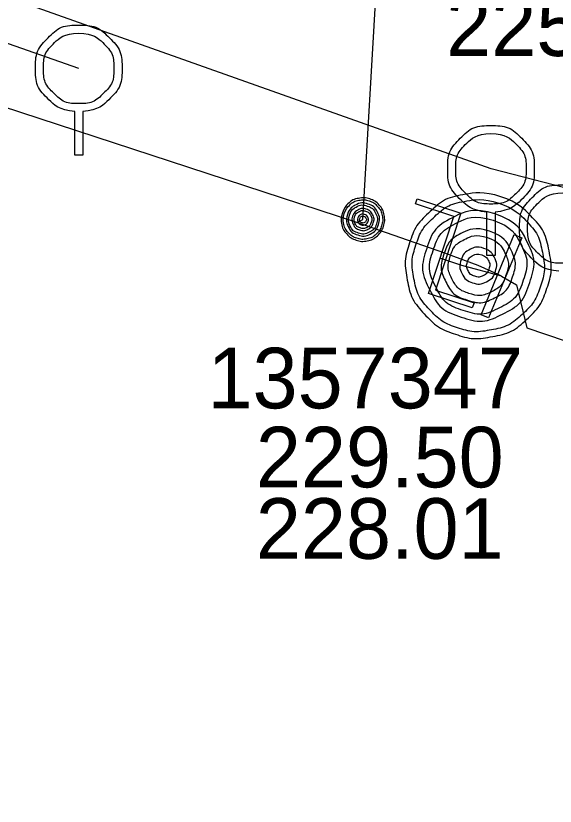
# Model space of a CAD drawing. Extents: x -595129 to -593591, y -1168385 to -1166898.
# Drawn here: x -594582.79 to -594570.33, y -1167194.67 to -1167176.41 of the extents above; entities that cross this region are included whole.
import ezdxf

# ---------------------------------------------------------------- set-up
doc = ezdxf.new("R2010")
doc.units = 0
for name, color, linetype in [('Default', 7, 'Continuous'), ('Identifikace', 7, 'Continuous'), ('Kanalizační stoka', 7, 'Continuous'), ('Kanalizační šachta', 7, 'Continuous'), ('Popis šachty', 7, 'Continuous'), ('V Lomový bod', 7, 'Continuous'), ('V Přípojka', 7, 'Continuous'), ('V Uzávěr', 7, 'Continuous'), ('V Řad', 7, 'Continuous')]:
    doc.layers.add(name, color=color, linetype=linetype)

msp = doc.modelspace()

# ---------------------------------------------------------------- linework, layer by layer
at = {"layer": 'Default'}
for points in [[(-594581.429, -1167178.626), (-594581.782, -1167178.597), (-594582.042, -1167178.337), (-594582.335, -1167178.046), (-594582.335, -1167177.632), (-594582.335, -1167177.216), (-594582.045, -1167176.923), (-594581.755, -1167176.63), (-594581.337, -1167176.63), (-594580.917, -1167176.63), (-594580.626, -1167176.923), (-594580.335, -1167177.216), (-594580.335, -1167177.632), (-594580.335, -1167178.046), (-594580.628, -1167178.337), (-594580.886, -1167178.597), (-594581.241, -1167178.626)], [(-594581.337, -1167176.816), (-594581.675, -1167176.816), (-594581.912, -1167177.053), (-594582.149, -1167177.29), (-594582.149, -1167177.628), (-594582.149, -1167177.966), (-594581.912, -1167178.203), (-594581.675, -1167178.441), (-594581.337, -1167178.441), (-594580.999, -1167178.441), (-594580.762, -1167178.203), (-594580.524, -1167177.966), (-594580.524, -1167177.628), (-594580.524, -1167177.29), (-594580.761, -1167177.053), (-594580.997, -1167176.816), (-594581.337, -1167176.816)], [(-594571.904, -1167180.946), (-594572.257, -1167180.917), (-594572.517, -1167180.657), (-594572.81, -1167180.366), (-594572.81, -1167179.952), (-594572.81, -1167179.536), (-594572.52, -1167179.243), (-594572.23, -1167178.95), (-594571.812, -1167178.95), (-594571.392, -1167178.95), (-594571.101, -1167179.243), (-594570.81, -1167179.536), (-594570.81, -1167179.952), (-594570.81, -1167180.366), (-594571.103, -1167180.657), (-594571.361, -1167180.917), (-594571.716, -1167180.946)], [(-594571.812, -1167179.136), (-594572.15, -1167179.136), (-594572.387, -1167179.373), (-594572.624, -1167179.61), (-594572.624, -1167179.948), (-594572.624, -1167180.286), (-594572.387, -1167180.523), (-594572.15, -1167180.761), (-594571.812, -1167180.761), (-594571.474, -1167180.761), (-594571.237, -1167180.523), (-594570.999, -1167180.286), (-594570.999, -1167179.948), (-594570.999, -1167179.61), (-594571.236, -1167179.373), (-594571.472, -1167179.136), (-594571.812, -1167179.136)], [(-594571.582, -1167180.594), (-594571.182, -1167180.727), (-594570.87, -1167181.057), (-594570.558, -1167181.387), (-594570.469, -1167181.84), (-594570.381, -1167182.293), (-594570.518, -1167182.708), (-594570.654, -1167183.121), (-594570.988, -1167183.429), (-594571.322, -1167183.737), (-594571.77, -1167183.821), (-594572.217, -1167183.906), (-594572.631, -1167183.769), (-594573.042, -1167183.633), (-594573.351, -1167183.299), (-594573.66, -1167182.965), (-594573.744, -1167182.518), (-594573.829, -1167182.072), (-594573.692, -1167181.659), (-594573.555, -1167181.244), (-594573.216, -1167180.932), (-594572.876, -1167180.621), (-594572.43, -1167180.541), (-594571.983, -1167180.462), (-594571.582, -1167180.594)], [(-594570.244, -1167182.316), (-594570.597, -1167182.287), (-594570.857, -1167182.027), (-594571.15, -1167181.736), (-594571.15, -1167181.322), (-594571.15, -1167180.906), (-594570.86, -1167180.613), (-594570.57, -1167180.32), (-594570.152, -1167180.32), (-594569.732, -1167180.32), (-594569.441, -1167180.613), (-594569.15, -1167180.906), (-594569.15, -1167181.322), (-594569.15, -1167181.736), (-594569.443, -1167182.027), (-594569.701, -1167182.287), (-594570.056, -1167182.316)], [(-594575.245, -1167180.963), (-594575.205, -1167180.844), (-594575.107, -1167180.75), (-594575.008, -1167180.657), (-594574.872, -1167180.63), (-594574.737, -1167180.604), (-594574.612, -1167180.645), (-594574.489, -1167180.685), (-594574.396, -1167180.785), (-594574.304, -1167180.885), (-594574.279, -1167181.019), (-594574.253, -1167181.153), (-594574.294, -1167181.277), (-594574.335, -1167181.4), (-594574.435, -1167181.493), (-594574.535, -1167181.585), (-594574.669, -1167181.611), (-594574.802, -1167181.636), (-594574.926, -1167181.595), (-594575.05, -1167181.554), (-594575.144, -1167181.453), (-594575.237, -1167181.351), (-594575.261, -1167181.217), (-594575.285, -1167181.084), (-594575.245, -1167180.963)], [(-594571.631, -1167180.743), (-594571.994, -1167180.623), (-594572.399, -1167180.695), (-594572.804, -1167180.766), (-594573.112, -1167181.049), (-594573.419, -1167181.332), (-594573.544, -1167181.708), (-594573.667, -1167182.082), (-594573.591, -1167182.486), (-594573.515, -1167182.89), (-594573.234, -1167183.194), (-594572.954, -1167183.497), (-594572.582, -1167183.62), (-594572.206, -1167183.744), (-594571.8, -1167183.668), (-594571.394, -1167183.591), (-594571.092, -1167183.312), (-594570.79, -1167183.033), (-594570.667, -1167182.659), (-594570.542, -1167182.282), (-594570.623, -1167181.872), (-594570.704, -1167181.461), (-594570.986, -1167181.162), (-594571.268, -1167180.863), (-594571.631, -1167180.743)], [(-594570.152, -1167180.506), (-594570.49, -1167180.506), (-594570.727, -1167180.743), (-594570.964, -1167180.98), (-594570.964, -1167181.318), (-594570.964, -1167181.656), (-594570.727, -1167181.893), (-594570.49, -1167182.131), (-594570.152, -1167182.131), (-594569.814, -1167182.131), (-594569.577, -1167181.893), (-594569.339, -1167181.656), (-594569.339, -1167181.318), (-594569.339, -1167180.98), (-594569.576, -1167180.743), (-594569.812, -1167180.506), (-594570.152, -1167180.506)], [(-594575.2, -1167180.978), (-594575.236, -1167181.087), (-594575.215, -1167181.208), (-594575.193, -1167181.329), (-594575.109, -1167181.421), (-594575.024, -1167181.513), (-594574.911, -1167181.551), (-594574.799, -1167181.588), (-594574.678, -1167181.565), (-594574.557, -1167181.542), (-594574.466, -1167181.458), (-594574.376, -1167181.374), (-594574.339, -1167181.262), (-594574.302, -1167181.15), (-594574.325, -1167181.029), (-594574.348, -1167180.907), (-594574.431, -1167180.817), (-594574.515, -1167180.726), (-594574.627, -1167180.689), (-594574.74, -1167180.652), (-594574.863, -1167180.676), (-594574.986, -1167180.701), (-594575.075, -1167180.785), (-594575.164, -1167180.87), (-594575.2, -1167180.978)], [(-594575.126, -1167181.003), (-594575.077, -1167180.853), (-594574.938, -1167180.784), (-594574.799, -1167180.715), (-594574.651, -1167180.764), (-594574.504, -1167180.812), (-594574.434, -1167180.951), (-594574.364, -1167181.09), (-594574.413, -1167181.238), (-594574.462, -1167181.385), (-594574.6, -1167181.455), (-594574.739, -1167181.525), (-594574.887, -1167181.476), (-594575.035, -1167181.428), (-594575.105, -1167181.29), (-594575.175, -1167181.152), (-594575.126, -1167181.003)], [(-594575.083, -1167181.018), (-594575.125, -1167181.147), (-594575.064, -1167181.269), (-594575.003, -1167181.39), (-594574.874, -1167181.432), (-594574.744, -1167181.475), (-594574.623, -1167181.414), (-594574.502, -1167181.353), (-594574.459, -1167181.223), (-594574.416, -1167181.094), (-594574.477, -1167180.973), (-594574.538, -1167180.851), (-594574.668, -1167180.809), (-594574.797, -1167180.766), (-594574.918, -1167180.826), (-594575.04, -1167180.887), (-594575.083, -1167181.018)], [(-594571.714, -1167180.991), (-594571.214, -1167181.156), (-594570.983, -1167181.619), (-594570.751, -1167182.083), (-594570.915, -1167182.577), (-594571.078, -1167183.07), (-594571.541, -1167183.303), (-594572.005, -1167183.535), (-594572.501, -1167183.372), (-594572.991, -1167183.21), (-594573.225, -1167182.746), (-594573.458, -1167182.283), (-594573.296, -1167181.79), (-594573.132, -1167181.296), (-594572.671, -1167181.061), (-594572.21, -1167180.827), (-594571.714, -1167180.991)], [(-594575.007, -1167181.042), (-594574.974, -1167180.942), (-594574.882, -1167180.896), (-594574.789, -1167180.85), (-594574.691, -1167180.882), (-594574.592, -1167180.915), (-594574.546, -1167181.007), (-594574.499, -1167181.1), (-594574.532, -1167181.199), (-594574.564, -1167181.297), (-594574.657, -1167181.343), (-594574.749, -1167181.39), (-594574.847, -1167181.358), (-594574.946, -1167181.325), (-594574.993, -1167181.233), (-594575.04, -1167181.141), (-594575.007, -1167181.042)], [(-594574.963, -1167181.056), (-594574.99, -1167181.137), (-594574.952, -1167181.212), (-594574.914, -1167181.287), (-594574.834, -1167181.313), (-594574.754, -1167181.34), (-594574.679, -1167181.302), (-594574.604, -1167181.264), (-594574.577, -1167181.184), (-594574.551, -1167181.104), (-594574.588, -1167181.029), (-594574.626, -1167180.954), (-594574.706, -1167180.927), (-594574.787, -1167180.901), (-594574.862, -1167180.938), (-594574.937, -1167180.976), (-594574.963, -1167181.056)], [(-594574.888, -1167181.081), (-594574.872, -1167181.031), (-594574.826, -1167181.008), (-594574.779, -1167180.985), (-594574.73, -1167181.001), (-594574.681, -1167181.017), (-594574.658, -1167181.064), (-594574.634, -1167181.11), (-594574.651, -1167181.16), (-594574.667, -1167181.208), (-594574.713, -1167181.232), (-594574.759, -1167181.255), (-594574.809, -1167181.239), (-594574.858, -1167181.222), (-594574.881, -1167181.176), (-594574.905, -1167181.13), (-594574.888, -1167181.081)], [(-594571.763, -1167181.136), (-594572.197, -1167180.993), (-594572.601, -1167181.197), (-594573.005, -1167181.401), (-594573.148, -1167181.834), (-594573.291, -1167182.266), (-594573.088, -1167182.671), (-594572.885, -1167183.076), (-594572.451, -1167183.22), (-594572.019, -1167183.363), (-594571.613, -1167183.159), (-594571.208, -1167182.955), (-594571.065, -1167182.522), (-594570.922, -1167182.09), (-594571.125, -1167181.685), (-594571.327, -1167181.28), (-594571.763, -1167181.136)], [(-594574.844, -1167181.096), (-594574.854, -1167181.126), (-594574.84, -1167181.155), (-594574.826, -1167181.184), (-594574.794, -1167181.195), (-594574.763, -1167181.205), (-594574.734, -1167181.19), (-594574.705, -1167181.175), (-594574.695, -1167181.145), (-594574.685, -1167181.113), (-594574.7, -1167181.085), (-594574.714, -1167181.056), (-594574.745, -1167181.046), (-594574.777, -1167181.036), (-594574.805, -1167181.05), (-594574.833, -1167181.064), (-594574.844, -1167181.096)], [(-594571.844, -1167181.388), (-594571.511, -1167181.498), (-594571.357, -1167181.807), (-594571.202, -1167182.116), (-594571.312, -1167182.446), (-594571.42, -1167182.775), (-594571.729, -1167182.93), (-594572.038, -1167183.084), (-594572.368, -1167182.975), (-594572.696, -1167182.867), (-594572.851, -1167182.559), (-594573.007, -1167182.25), (-594572.899, -1167181.921), (-594572.79, -1167181.591), (-594572.483, -1167181.435), (-594572.176, -1167181.278), (-594571.844, -1167181.388)], [(-594571.893, -1167181.535), (-594572.161, -1167181.447), (-594572.411, -1167181.573), (-594572.662, -1167181.699), (-594572.751, -1167181.967), (-594572.839, -1167182.235), (-594572.713, -1167182.486), (-594572.587, -1167182.736), (-594572.319, -1167182.825), (-594572.052, -1167182.913), (-594571.801, -1167182.787), (-594571.55, -1167182.661), (-594571.461, -1167182.393), (-594571.372, -1167182.125), (-594571.498, -1167181.875), (-594571.624, -1167181.624), (-594571.893, -1167181.535)], [(-594571.975, -1167181.785), (-594571.808, -1167181.84), (-594571.731, -1167181.995), (-594571.654, -1167182.149), (-594571.708, -1167182.313), (-594571.762, -1167182.478), (-594571.917, -1167182.555), (-594572.072, -1167182.633), (-594572.237, -1167182.578), (-594572.4, -1167182.525), (-594572.478, -1167182.37), (-594572.556, -1167182.215), (-594572.501, -1167182.051), (-594572.447, -1167181.887), (-594572.293, -1167181.809), (-594572.139, -1167181.731), (-594571.975, -1167181.785)], [(-594572.024, -1167181.934), (-594572.127, -1167181.9), (-594572.223, -1167181.947), (-594572.319, -1167181.994), (-594572.354, -1167182.1), (-594572.388, -1167182.202), (-594572.339, -1167182.299), (-594572.29, -1167182.396), (-594572.188, -1167182.43), (-594572.083, -1167182.465), (-594571.987, -1167182.415), (-594571.892, -1167182.366), (-594571.858, -1167182.264), (-594571.823, -1167182.158), (-594571.871, -1167182.063), (-594571.919, -1167181.969), (-594572.024, -1167181.934)]]:
    msp.add_open_spline(points, degree=3, dxfattribs=at)
at = {"layer": 'Kanalizační stoka'}
for points in [[(-594581.335, -1167177.63), (-594585.004, -1167176.349), (-594585.196, -1167176.281), (-594585.322, -1167176.237), (-594585.536, -1167176.162), (-594585.633, -1167176.128), (-594586.112, -1167175.961), (-594586.143, -1167175.95), (-594595.165, -1167172.799), (-594595.225, -1167172.778), (-594595.315, -1167172.747), (-594596.45, -1167172.361), (-594596.806, -1167172.241), (-594596.832, -1167172.232), (-594602.334, -1167170.372), (-594602.677, -1167170.255), (-594602.774, -1167170.222), (-594607.438, -1167168.638), (-594607.714, -1167168.544), (-594607.849, -1167168.498), (-594608.386, -1167168.316), (-594608.795, -1167168.179), (-594608.882, -1167168.15), (-594620.923, -1167164.112)], [(-594571.81, -1167179.95), (-594584.475, -1167175.456), (-594584.636, -1167175.399), (-594584.701, -1167175.376), (-594586.64, -1167174.688), (-594586.7, -1167174.667), (-594590.942, -1167173.162), (-594590.959, -1167173.156), (-594591.441, -1167172.985), (-594598.553, -1167170.462)], [(-594549.99, -1167185.56), (-594551.901, -1167185.069), (-594552.188, -1167184.995), (-594552.895, -1167184.813), (-594562.033, -1167182.464), (-594562.406, -1167182.368), (-594562.581, -1167182.323), (-594565.606, -1167181.546), (-594566.009, -1167181.442), (-594566.968, -1167181.195), (-594571.81, -1167179.95)]]:
    msp.add_lwpolyline(points, dxfattribs=at)
at = {"layer": 'Kanalizační šachta'}
for points in [[(-594581.241, -1167178.626), (-594581.241, -1167179.63), (-594581.429, -1167179.63), (-594581.429, -1167178.626)], [(-594571.716, -1167180.946), (-594571.716, -1167181.95), (-594571.904, -1167181.95), (-594571.904, -1167180.946)]]:
    msp.add_lwpolyline(points, dxfattribs=at)
at = {"layer": 'V Lomový bod'}
msp.add_lwpolyline([(-594573.094, -1167182.751), (-594572.203, -1167183.043), (-594572.242, -1167183.162), (-594573.252, -1167182.83), (-594572.666, -1167181.049), (-594573.557, -1167180.757), (-594573.518, -1167180.638), (-594572.509, -1167180.969), (-594573.094, -1167182.751)], dxfattribs=at)
at = {"layer": 'V Přípojka'}
msp.add_lwpolyline([(-594574.91, -1167181.19), (-594574.769, -1167181.12), (-594574.314, -1167173.344)], dxfattribs=at)
at = {"layer": 'V Uzávěr'}
msp.add_lwpolyline([(-594571.274, -1167181.467), (-594571.1, -1167181.539), (-594571.865, -1167183.389), (-594572.039, -1167183.317), (-594571.274, -1167181.467)], dxfattribs=at)
at = {"layer": 'V Řad'}
for points in [[(-594572.88, -1167181.9), (-594574.91, -1167181.19), (-594583.978, -1167178.227), (-594588.03, -1167176.9), (-594590.65, -1167176.05), (-594596.48, -1167174.14), (-594601.81, -1167172.42), (-594602.45, -1167172.21), (-594603.38, -1167171.91), (-594613.31, -1167168.64), (-594614.19, -1167168.34), (-594630.279, -1167163.083), (-594631.562, -1167162.648)], [(-594571.57, -1167182.429), (-594571.641, -1167182.39), (-594572.105, -1167182.184), (-594572.88, -1167181.9)], [(-594571.57, -1167182.429), (-594572.483, -1167182.178), (-594572.967, -1167182.017)], [(-594571.57, -1167182.43), (-594571.22, -1167182.63), (-594570.98, -1167183.62), (-594567.849, -1167184.686), (-594560.74, -1167187.087), (-594557.65, -1167188.08), (-594554.87, -1167189.024), (-594546.542, -1167191.952), (-594538.93, -1167194.67)]]:
    msp.add_lwpolyline(points, dxfattribs=at)

# ---------------------------------------------------------------- texts
at = {"layer": 'Identifikace'}
msp.add_text('1357347', height=1.4, dxfattribs=at).set_placement((-594578.361, -1167185.481))
at = {"layer": 'Popis šachty'}
for s, p in [('225.77', (-594572.846, -1167177.343)), ('229.50', (-594577.243, -1167187.306)), ('228.01', (-594577.243, -1167188.956))]:
    msp.add_text(s, height=1.4, dxfattribs=at).set_placement(p)

doc.saveas('drawing.dxf')
